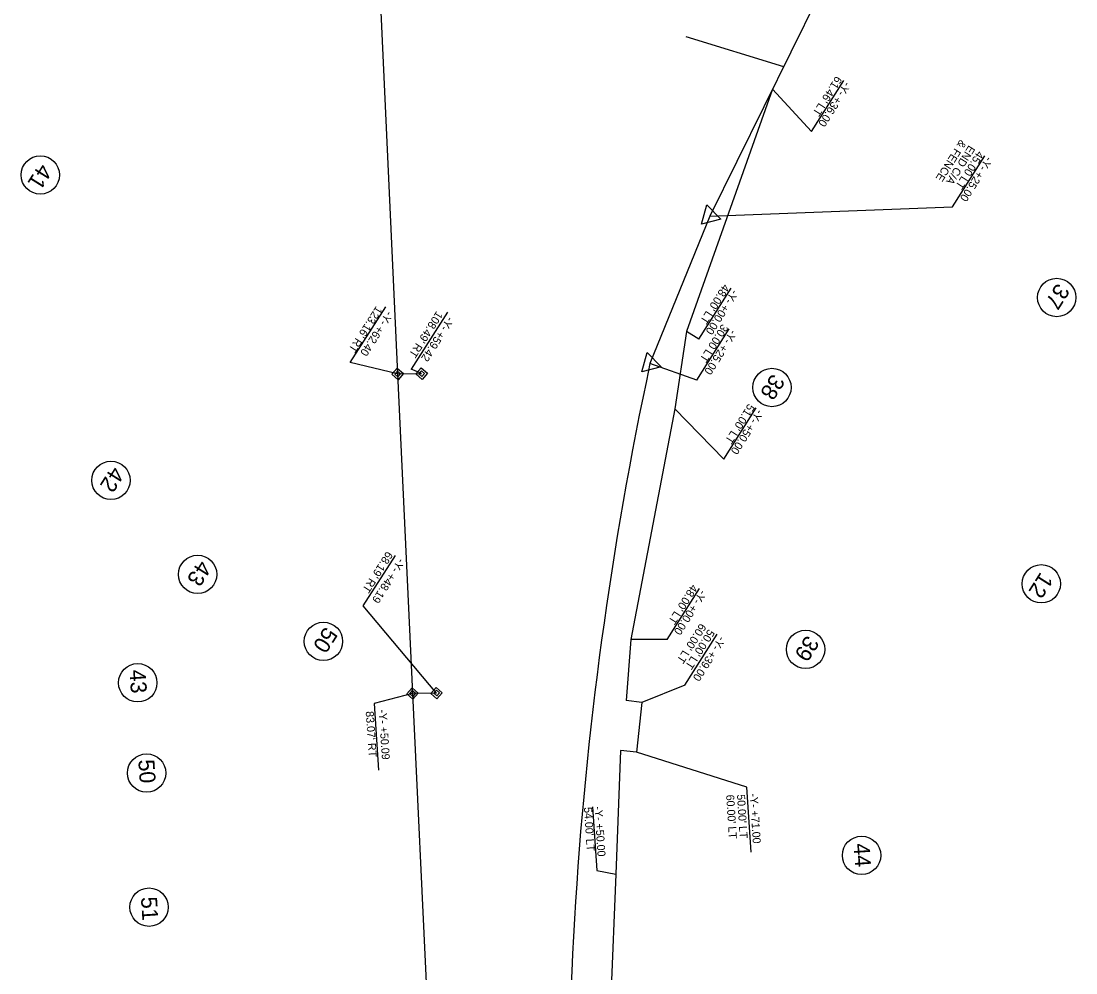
# Model space of a CAD drawing. Extents: x 1779796 to 1783527, y 810952 to 815815.
# Drawn here: x 1780667 to 1781326, y 811628 to 812223 of the extents above; entities that cross this region are included whole.
import ezdxf

# ---------------------------------------------------------------- set-up
doc = ezdxf.new("R2010")
doc.units = 0
for name, color, linetype in [('Prop Easement Aerial Utility', 7, 'Continuous'), ('Prop Easement Construction', 7, 'Continuous'), ('Prop Easement Construction Station Offsets', 7, 'Continuous'), ('Prop Easement Permanent Utility', 7, 'Continuous'), ('Prop Easement Permanent Utility Station Offsets', 7, 'Continuous'), ('Prop Fence Woven Wire', 7, 'Continuous'), ('Prop Parcel Number CELL', 7, 'Continuous'), ('Prop Parcel Number Text', 7, 'Continuous'), ('Prop ROW Marker CELL', 7, 'Continuous'), ('Prop ROW Permanent Easement CELL', 7, 'Continuous'), ('Prop ROW RW CA Lines', 7, 'Continuous'), ('Prop ROW RW Lines', 7, 'Continuous'), ('Prop ROW Station Offsets', 7, 'Continuous'), ('Scratch_Level_1', 7, 'Continuous')]:
    doc.layers.add(name, color=color, linetype=linetype)

msp = doc.modelspace()

# ---------------------------------------------------------------- linework, layer by layer
at = {"layer": 'Prop Easement Aerial Utility'}
msp.add_line((1780902.31, 812002.16), (1780911.62, 811802.39), dxfattribs=at)
at = {"layer": 'Prop Easement Construction'}
for p, q in [((1781082.88, 812028.72), (1781075.54, 811980.25)), ((1781075.54, 811980.25), (1781047.97, 811836.04)), ((1781047.97, 811836.04), (1781045.08, 811797.92)), ((1781055.01, 811796.73), (1781045.08, 811797.92)), ((1781055.01, 811796.73), (1781051.51, 811765.75)), ((1781041.56, 811766.8), (1781038.69, 811689.52)), ((1781051.51, 811765.75), (1781041.56, 811766.8)), ((1781038.69, 811689.52), (1781035.38, 811610.48))]:
    msp.add_line(p, q, dxfattribs=at)
msp.add_lwpolyline([(1781136.5, 812180.19), (1781082.88, 812028.72)], dxfattribs=at)
at = {"layer": 'Prop Easement Construction Station Offsets'}
for p, q in [((1781160.88, 812153.77), (1781181.12, 812185.67)), ((1781160.88, 812153.77), (1781136.5, 812180.19)), ((1781090.52, 812023.82), (1781110.76, 812055.72)), ((1781106.18, 811948.97), (1781075.54, 811980.25)), ((1781106.18, 811948.97), (1781126.43, 811980.87)), ((1781070.65, 811836.09), (1781090.9, 811868)), ((1781081.85, 811807.57), (1781102.09, 811839.48)), ((1781070.65, 811836.09), (1781047.97, 811836.04)), ((1781123.16, 811703.17), (1781120.58, 811743.8)), ((1781024.16, 811731.5), (1781026.69, 811691.73)), ((1781026.69, 811691.73), (1781038.69, 811689.52))]:
    msp.add_line(p, q, dxfattribs=at)
for points in [[(1781090.52, 812023.82), (1781082.88, 812028.72)], [(1781081.85, 811807.57), (1781055.01, 811796.73)], [(1781120.58, 811743.8), (1781051.51, 811765.75)]]:
    msp.add_lwpolyline(points, dxfattribs=at)
at = {"layer": 'Prop Easement Permanent Utility'}
for p, q in [((1780883.69, 812401.27), (1780902.31, 812002.16)), ((1780902.31, 812002.16), (1780917.31, 812002.38)), ((1780926.63, 811802.62), (1780911.62, 811802.39)), ((1780911.62, 811802.39), (1780921, 811601.4))]:
    msp.add_line(p, q, dxfattribs=at)
at = {"layer": 'Prop Easement Permanent Utility Station Offsets'}
for p, q in [((1780872.69, 812009.32), (1780894.97, 812044.18)), ((1780933.47, 812040.76), (1780910.69, 812005.06)), ((1780902.31, 812002.16), (1780872.69, 812009.32)), ((1780917.31, 812002.38), (1780910.69, 812005.06)), ((1780880.7, 811857.16), (1780900.86, 811888.69)), ((1780926.63, 811802.62), (1780880.7, 811857.16)), ((1780911.62, 811802.39), (1780887.62, 811796.21)), ((1780887.62, 811796.21), (1780890.43, 811754.5))]:
    msp.add_line(p, q, dxfattribs=at)
at = {"layer": 'Prop Fence Woven Wire'}
msp.add_line((1781178.22, 812264.63), (1781097.31, 812100.86), dxfattribs=at)
at = {"layer": 'Prop Parcel Number CELL'}
for p, q in [((1780678.97, 812126.55), (1780678.97, 812126.55)), ((1781314.19, 812049.94), (1781314.19, 812049.94)), ((1781136.23, 811993.67), (1781136.23, 811993.67)), ((1780723.13, 811935.63), (1780723.13, 811935.63)), ((1780777.3, 811876.83), (1780777.3, 811876.83)), ((1781304.56, 811870.96), (1781304.56, 811870.96)), ((1780855.92, 811834.97), (1780855.92, 811834.97)), ((1781157.24, 811829.95), (1781157.24, 811829.95)), ((1780739.9, 811809.07), (1780739.9, 811809.07)), ((1780745.41, 811752.64), (1780745.41, 811752.64)), ((1781192.23, 811701.17), (1781192.23, 811701.17)), ((1780746.94, 811668.79), (1780746.94, 811668.79))]:
    msp.add_line(p, q, dxfattribs=at)
for centre in [(1780678.97, 812126.55), (1781314.19, 812049.94), (1781136.23, 811993.67), (1780723.13, 811935.63), (1780777.3, 811876.83), (1781304.56, 811870.96), (1780855.92, 811834.97), (1781157.24, 811829.95), (1780739.9, 811809.07), (1780745.41, 811752.64), (1781192.23, 811701.17), (1780746.94, 811668.79)]:
    msp.add_circle(centre, 12, dxfattribs=at)
at = {"layer": 'Prop ROW Marker CELL'}
for p, q in [((1781097.31, 812100.86), (1781097.31, 812100.86)), ((1781060.01, 812008.59), (1781060.01, 812008.59))]:
    msp.add_line(p, q, dxfattribs=at)
for points in [[(1781095.47, 812107.83), (1781104.26, 812098.97), (1781092.2, 812095.77)], [(1781058.18, 812015.56), (1781066.96, 812006.7), (1781054.9, 812003.5)]]:
    msp.add_lwpolyline(points, close=True, dxfattribs=at)
at = {"layer": 'Prop ROW Permanent Easement CELL'}
for p, q in [((1780902.31, 812002.16), (1780902.31, 812002.16)), ((1780917.31, 812002.38), (1780917.31, 812002.38)), ((1780911.62, 811802.39), (1780911.62, 811802.39)), ((1780926.63, 811802.62), (1780926.63, 811802.62))]:
    msp.add_line(p, q, dxfattribs=at)
for points in [[(1780902.53, 811998.57), (1780898.71, 812001.93), (1780902.08, 812005.75), (1780905.9, 812002.39)], [(1780902.42, 812000.36), (1780900.51, 812002.05), (1780902.19, 812003.96), (1780904.1, 812002.27)], [(1780917.54, 811998.79), (1780913.72, 812002.15), (1780917.08, 812005.97), (1780920.9, 812002.61)], [(1780917.42, 812000.58), (1780915.51, 812002.26), (1780917.2, 812004.17), (1780919.11, 812002.49)], [(1780911.85, 811798.79), (1780908.03, 811802.16), (1780911.4, 811805.98), (1780915.22, 811802.62)], [(1780926.85, 811799.03), (1780923.03, 811802.39), (1780926.4, 811806.21), (1780930.22, 811802.85)], [(1780911.74, 811800.59), (1780909.83, 811802.27), (1780911.51, 811804.18), (1780913.42, 811802.5)], [(1780926.74, 811800.82), (1780924.83, 811802.5), (1780926.51, 811804.41), (1780928.42, 811802.73)]]:
    msp.add_lwpolyline(points, close=True, dxfattribs=at)
at = {"layer": 'Prop ROW RW CA Lines'}
msp.add_line((1781178.22, 812264.63), (1781097.31, 812100.86), dxfattribs=at)
at = {"layer": 'Prop ROW RW Lines'}
msp.add_line((1781097.31, 812100.86), (1781060.01, 812008.59), dxfattribs=at)
msp.add_arc((1783308.81, 811525.98), 2300, 167.88753, 185.35942, dxfattribs=at)
at = {"layer": 'Prop ROW Station Offsets'}
for p, q in [((1781249.04, 812106.55), (1781269.34, 812138.55)), ((1781097.31, 812100.86), (1781249.04, 812106.55)), ((1781089.26, 811998.28), (1781109.57, 812030.28)), ((1781089.26, 811998.28), (1781060.01, 812008.59))]:
    msp.add_line(p, q, dxfattribs=at)
at = {"layer": 'Scratch_Level_1'}
msp.add_line((1781082.45, 812213.17), (1781143.51, 812194.32), dxfattribs=at)

# ---------------------------------------------------------------- texts
at = {"layer": 'Prop Easement Construction Station Offsets'}
for s, rotation, p in [("61.46' LT", 237.60153, (1781176.26, 812188.74)), ('-Y- +36.00', 237.60153, (1781181.75, 812185.26)), ("48.00' LT", 237.60153, (1781105.9, 812058.78)), ('-Y- +00.00', 237.60153, (1781111.38, 812055.3)), ("51.00' LT", 237.60153, (1781121.56, 811983.93)), ('-Y- +50.00', 237.60153, (1781127.05, 811980.45)), ("48.00' LT", 237.60153, (1781086.03, 811871.06)), ('-Y- +00.00', 237.60153, (1781091.52, 811867.58)), ("60.00' LT", 237.60153, (1781091.37, 811846.6)), ("50.00' LT", 237.60153, (1781096.59, 811842.94)), ('-Y- +39.00', 237.60153, (1781103.35, 811838.66)), ("50.00' LT", 273.6363, (1781114.35, 811739.25)), ('-Y- +71.00', 273.6363, (1781122.34, 811739.76)), ("60.00' LT", 273.6363, (1781107.58, 811738.98)), ("54.00' LT", 273.63495, (1781018.75, 811731.25)), ('-Y- +50.00', 273.63495, (1781025.29, 811731.67))]:
    msp.add_text(s, height=5, rotation=rotation, dxfattribs=at).set_placement(p)
at = {"layer": 'Prop Easement Permanent Utility Station Offsets'}
for s, rotation, p in [("123.16' RT", 237.40698, (1780888.92, 812044.94)), ('-Y- +62.40', 237.40698, (1780895.57, 812041.87)), ("108.49' RT", 237.40698, (1780926.65, 812041.75)), ('-Y- +59.42', 237.46065, (1780933.6, 812038.45)), ("68.19' RT", 237.40698, (1780895.51, 811891.65)), ('-Y- +48.19', 237.40698, (1780902.96, 811887.34)), ('-Y- +50.09', 273.84989, (1780890.4, 811792.2)), ("83.07' RT", 273.84989, (1780882.33, 811791.15))]:
    msp.add_text(s, height=5, rotation=rotation, dxfattribs=at).set_placement(p)
at = {"layer": 'Prop Parcel Number Text'}
for s, rotation, p in [('41', 237.60039, (1780678.62, 812134.28)), ('37', 237.60039, (1781314.47, 812059.44)), ('38', 237.60039, (1781136.46, 812002.82)), ('42', 237.60039, (1780723.81, 811945.03)), ('43', 237.60039, (1780778.19, 811886.33)), ('12', 237.60039, (1781304.18, 811878.79)), ('50', 237.60039, (1780856.93, 811844.65)), ('39', 237.60039, (1781157.9, 811839.33)), ('43', 273.6363, (1780734.73, 811817.05)), ('50', 273.6363, (1780740.22, 811760.84)), ('44', 273.6363, (1781187.27, 811708.48)), ('51', 273.6363, (1780741.87, 811675.02))]:
    msp.add_text(s, height=10, rotation=rotation, dxfattribs=at).set_placement(p)
at = {"layer": 'Prop ROW Station Offsets'}
for s, p in [('& FENCE', (1781253.85, 812148.96)), ('END C/A', (1781259.33, 812145.48)), ('45.00 LT', (1781264.82, 812142)), ('-Y- +25.00', (1781270.31, 812138.51)), ('30.00 LT', (1781105.05, 812033.73)), ('-Y- +25.00', (1781110.53, 812030.25))]:
    msp.add_text(s, height=5, rotation=237.60153, dxfattribs=at).set_placement(p)

doc.saveas('drawing.dxf')
